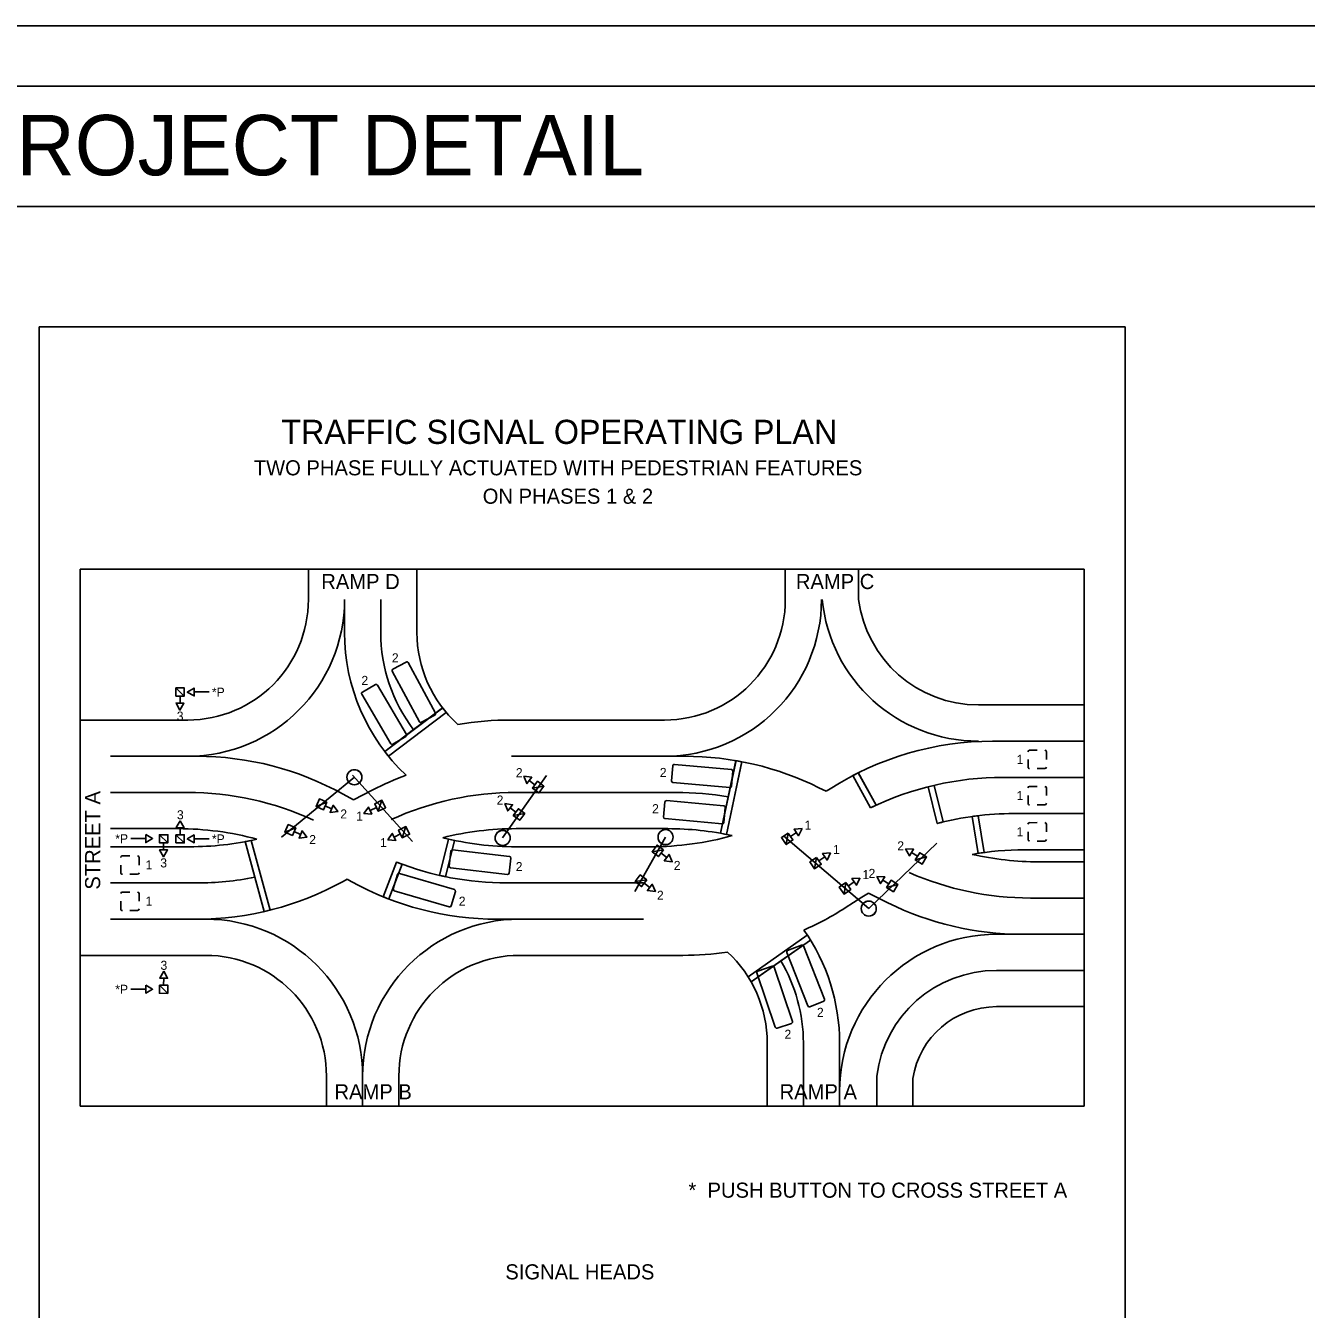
# Model space of a CAD drawing. Extents: x 515543 to 517243, y 660510 to 662861.
# Drawn here: x 516181 to 516712, y 662329 to 662861 of the extents above; entities that cross this region are included whole.
import ezdxf

# ---------------------------------------------------------------- set-up
doc = ezdxf.new("R2010")
doc.units = 0
for name, color, linetype in [('ANNO-SHT', 7, 'Continuous'), ('Default', 7, 'Continuous'), ('DRAINAGE', 7, 'Continuous'), ('Level 1', 7, 'Continuous'), ('Level 62', 7, 'Continuous'), ('SHT-BDR', 7, 'Continuous'), ('SHT-BNDRY', 7, 'Continuous'), ('Signal Design', 7, 'Continuous')]:
    doc.layers.add(name, color=color, linetype=linetype)

# ---------------------------------------------------------------- blocks, each defined once
blk = doc.blocks.new('SC47208')
at = {"layer": 'Level 1'}
blk.add_line((0, 0), (0, 0), dxfattribs=at)
blk = doc.blocks.new('A$C10762150')
at = {"layer": 'Signal Design'}
for p, q in [((-400, -432), (400, 432)), ((-400, -432), (400, 432)), ((-1127, -29), (-415, -14))]:
    blk.add_line(p, q, dxfattribs=at)
for points in [[(-1820, -44), (-1118, -428), (-1135, 370), (-1820, -44), (-1820, -44)], [(-400, -432), (418, -415), (400, 432), (-418, 415), (-400, -432), (-400, -432)]]:
    blk.add_lwpolyline(points, dxfattribs=at)
blk = doc.blocks.new('A$C57205C4C')
at = {"layer": 'Signal Design'}
blk.add_blockref('A$C10762150', (0, 0), dxfattribs=at)

msp = doc.modelspace()

# ---------------------------------------------------------------- linework, layer by layer
at = {"layer": 'Default'}
for p, q in [((516186.87, 662735.88), (516636.87, 662735.88)), ((516186.87, 662735.88), (516186.87, 661900.05)), ((516636.87, 662735.88), (516636.87, 661900.05)), ((516203.87, 662635.52), (516619.86, 662635.52)), ((516203.87, 662413.02), (516203.87, 662635.52)), ((516298.37, 662623.02), (516298.37, 662635.52)), ((516343.37, 662623.02), (516343.37, 662635.52)), ((516495.99, 662623.02), (516495.99, 662635.52)), ((516526.38, 662623.02), (516526.38, 662635.52)), ((516619.86, 662413.02), (516619.86, 662635.52)), ((516313.37, 662609.27), (516313.37, 662623.02)), ((516328.37, 662609.27), (516328.37, 662623.02)), ((516343.37, 662609.27), (516343.37, 662623.02)), ((516251.05, 662584.65), (516257.3, 662584.65)), ((516575.99, 662579.27), (516619.86, 662579.27)), ((516248.37, 662573.02), (516203.87, 662573.02)), ((516354.03, 662578.11), (516330.01, 662560.01)), ((516355.54, 662576.12), (516331.55, 662558.04)), ((516341.99, 662569.04), (516354.03, 662578.11)), ((516393.37, 662573.02), (516382.54, 662573.02)), ((516393.37, 662573.02), (516445.99, 662573.02)), ((516330.01, 662560.01), (516341.99, 662569.04)), ((516581.91, 662564.27), (516619.86, 662564.27)), ((516252.13, 662558.02), (516216.37, 662558.02)), ((516393.37, 662558.02), (516382.54, 662558.02)), ((516393.37, 662558.02), (516454.33, 662558.02)), ((516600.36, 662560.51), (516597.18, 662560.5)), ((516604.18, 662556.71), (516604.17, 662559.89)), ((516469.14, 662526.18), (516475.58, 662556.31)), ((516471.58, 662525.65), (516478.03, 662555.78)), ((516475.56, 662556.21), (516472.36, 662541.24)), ((516596.56, 662556.69), (516596.57, 662553.52)), ((516603.55, 662552.9), (516600.38, 662552.89)), ((516531.33, 662536.64), (516523.97, 662550.06)), ((516533.59, 662537.71), (516526.16, 662551.27)), ((516619.86, 662549.27), (516586.29, 662549.27)), ((516216.37, 662543.02), (516248.25, 662543.02)), ((516312.73, 662542.35), (516317.12, 662539.92)), ((516325.1, 662544.05), (516317.12, 662539.92)), ((516450.81, 662543.02), (516384.45, 662543.02)), ((516472.36, 662541.24), (516469.14, 662526.18)), ((516512.89, 662543.51), (516509.92, 662544.98)), ((516512.89, 662543.51), (516514.58, 662544.59)), ((516558.94, 662530.18), (516555.2, 662545.37)), ((516561.36, 662530.79), (516557.63, 662545.96)), ((516596.56, 662541.69), (516596.57, 662538.52)), ((516600.36, 662545.51), (516597.18, 662545.5)), ((516604.18, 662541.71), (516604.17, 662544.89)), ((516603.55, 662537.9), (516600.38, 662537.89)), ((516575.86, 662517.79), (516573.42, 662533.08)), ((516578.34, 662518.15), (516575.9, 662533.4)), ((516619.86, 662534.27), (516590.67, 662534.27)), ((516600.36, 662530.51), (516597.18, 662530.5)), ((516216.37, 662528.02), (516244.37, 662528.02)), ((516394.62, 662528.02), (516384.45, 662528.02)), ((516447.3, 662528.02), (516394.62, 662528.02)), ((516596.56, 662526.69), (516596.57, 662523.52)), ((516604.18, 662526.71), (516604.17, 662529.89)), ((516216.37, 662520.52), (516249.2, 662520.52)), ((516231.02, 662523.92), (516224.77, 662523.92)), ((516251.05, 662523.82), (516257.3, 662523.82)), ((516272.18, 662522.65), (516280.05, 662493.67)), ((516276.2, 662507.86), (516272.18, 662522.65)), ((516274.64, 662523.13), (516282.49, 662494.26)), ((516356.48, 662523.69), (516352.75, 662508.65)), ((516358.92, 662523.15), (516355.19, 662508.12)), ((516440.38, 662520.52), (516384.45, 662520.52)), ((516437.24, 662520.52), (516433.51, 662520.52)), ((516603.55, 662522.9), (516600.38, 662522.89)), ((516224.44, 662516.75), (516221.26, 662516.74)), ((516228.26, 662512.96), (516228.25, 662516.13)), ((516619.86, 662519.27), (516595.06, 662519.27)), ((516220.64, 662512.93), (516220.65, 662509.76)), ((516227.64, 662509.15), (516224.46, 662509.14)), ((516334.88, 662514.17), (516329.33, 662499.81)), ((516337.21, 662513.28), (516331.66, 662498.91)), ((516619.86, 662514.27), (516601.1, 662514.27)), ((516216.37, 662505.52), (516252.13, 662505.52)), ((516280.05, 662493.67), (516276.2, 662507.86)), ((516312.73, 662506.19), (516314.41, 662507.12)), ((516314.41, 662507.12), (516316.08, 662506.19)), ((516437.24, 662505.52), (516380.57, 662505.52)), ((516224.44, 662501.75), (516221.26, 662501.74)), ((516228.26, 662497.96), (516228.25, 662501.13)), ((516520.86, 662495.2), (516527.73, 662499.59)), ((516538.48, 662497.31), (516530.47, 662501.29)), ((516619.86, 662499.27), (516597.58, 662499.27)), ((516220.64, 662497.93), (516220.65, 662494.76)), ((516227.64, 662494.15), (516224.46, 662494.14)), ((516252.13, 662490.52), (516216.37, 662490.52)), ((516376.69, 662490.52), (516437.24, 662490.52)), ((516505.1, 662483.95), (516480.54, 662466.68)), ((516583.49, 662484.27), (516594.06, 662484.27)), ((516594.06, 662484.27), (516619.86, 662484.27)), ((516506.44, 662481.84), (516481.83, 662464.53)), ((516494.14, 662473.19), (516506.44, 662481.84)), ((516255.87, 662475.52), (516203.87, 662475.52)), ((516385.87, 662475.52), (516453.53, 662475.52)), ((516481.83, 662464.53), (516494.14, 662473.19)), ((516583.49, 662469.27), (516619.86, 662469.27)), ((516231.02, 662461.53), (516224.77, 662461.53)), ((516583.49, 662454.27), (516619.86, 662454.27)), ((516488.49, 662439.27), (516488.49, 662413.02)), ((516503.49, 662439.27), (516503.49, 662413.02)), ((516518.49, 662439.27), (516518.49, 662413.02)), ((516305.87, 662425.52), (516305.87, 662413.02)), ((516320.87, 662425.52), (516320.87, 662413.02)), ((516335.87, 662425.52), (516335.87, 662413.02)), ((516533.88, 662425.52), (516533.88, 662413.02)), ((516548.88, 662424.49), (516548.88, 662413.02)), ((516203.87, 662413.02), (516619.86, 662413.02))]:
    msp.add_line(p, q, dxfattribs=at)
for points in [[(516338.92, 662597.07), (516333.41, 662594.11)], [(516351.02, 662575.9), (516339.76, 662596.82)], [(516333.16, 662593.26), (516344.41, 662572.35)], [(516248.21, 662584.62), (516251.07, 662583.01), (516251.04, 662586.28), (516248.21, 662584.62), (516248.21, 662584.62)], [(516320.52, 662583.71), (516332.52, 662563.21)], [(516326.14, 662587.72), (516320.75, 662584.56)], [(516338.99, 662567), (516327, 662587.5)], [(516353.97, 662578.06), (516330.01, 662560.01)], [(516331.55, 662558.04), (516355.54, 662576.12)], [(516345.26, 662572.09), (516350.76, 662575.06)], [(516333.38, 662562.99), (516338.77, 662566.15)], [(516449.34, 662554.09), (516448.78, 662547.87)], [(516473.68, 662552.52), (516450.02, 662554.66)], [(516475.56, 662556.21), (516469.12, 662526.1)], [(516471.58, 662525.64), (516478.02, 662555.76), (516478.02, 662555.76)], [(516473.68, 662545.61), (516474.24, 662551.84)], [(516449.35, 662547.19), (516473, 662545.05)], [(516523.98, 662550.04), (516531.33, 662536.64)], [(516533.59, 662537.71), (516526.21, 662551.18)], [(516555.2, 662545.37), (516558.94, 662530.18)], [(516561.36, 662530.79), (516557.63, 662545.96)], [(516446.13, 662539.08), (516445.57, 662532.85)], [(516470.47, 662537.5), (516446.81, 662539.64)], [(516470.47, 662530.6), (516471.03, 662536.82)], [(516446.14, 662532.17), (516469.79, 662530.03)], [(516573.42, 662533.08), (516575.86, 662517.79)], [(516578.34, 662518.15), (516575.9, 662533.4)], [(516231.03, 662525.55), (516231, 662522.28), (516233.86, 662523.89), (516231.03, 662525.55), (516231.03, 662525.55)], [(516248.21, 662523.79), (516251.07, 662522.18), (516251.04, 662525.46), (516248.21, 662523.79), (516248.21, 662523.79)], [(516272.18, 662522.65), (516280.05, 662493.67)], [(516282.49, 662494.26), (516274.64, 662523.13)], [(516356.48, 662523.69), (516352.75, 662508.65)], [(516355.19, 662508.12), (516358.92, 662523.15)], [(516357.42, 662518.74), (516356.69, 662512.53)], [(516381.7, 662516.54), (516358.11, 662519.29)], [(516381.52, 662509.64), (516382.25, 662515.84)], [(516334.88, 662514.17), (516329.34, 662499.83)], [(516331.66, 662498.91), (516337.21, 662513.28)], [(516358.88, 662502.81), (516336.1, 662509.51)], [(516357.24, 662511.84), (516380.83, 662509.09)], [(516335.32, 662509.09), (516333.56, 662503.09)], [(516333.98, 662502.32), (516356.76, 662495.62)], [(516357.54, 662496.04), (516359.3, 662502.04)], [(516505.1, 662483.95), (516480.54, 662466.68)], [(516481.83, 662464.53), (516506.44, 662481.84)], [(516502.75, 662479.8), (516496.93, 662477.5)], [(516512.3, 662457.37), (516503.56, 662479.45)], [(516496.58, 662476.69), (516505.33, 662454.61)], [(516484.24, 662468.22), (516491.84, 662445.72)], [(516490.56, 662471.01), (516484.63, 662469.01)], [(516498.95, 662448.12), (516491.35, 662470.62)], [(516231.03, 662463.17), (516231, 662459.89), (516233.86, 662461.51), (516231.03, 662463.17), (516231.03, 662463.17)], [(516506.14, 662454.26), (516511.95, 662456.56)], [(516492.63, 662445.33), (516498.55, 662447.33)]]:
    msp.add_lwpolyline(points, dxfattribs=at)
for centre, radius, start, end in [((516248.37, 662623.02), 50, 270, 0), ((516248.37, 662623.02), 65, 270, 0), ((516445.99, 662623.02), 50, 270, 0), ((516445.99, 662623.02), 65, 270, 0), ((516575.99, 662629.27), 65, 185.5177, 270), ((516575.99, 662629.27), 50, 187.1808, 270), ((516394.62, 662609.27), 81.25, 180, 226.6887), ((516394.62, 662609.27), 66.25, 180, 217.3982), ((516394.62, 662609.27), 51.25, 180, 227.9111), ((516339.21, 662596.52), 0.625, 28.2805, 118.2805), ((516333.71, 662593.56), 0.625, 118.2805, 208.2805), ((516321.06, 662584.02), 0.625, 120.344, 210.344), ((516326.46, 662587.18), 0.625, 30.344, 120.344), ((516350.47, 662575.61), 0.625, 298.2805, 28.2805), ((516394.62, 662609.27), 51.25, 217.5151, 220.3119), ((516382.54, 662433.02), 140, 90, 99.1538), ((516344.96, 662572.64), 0.625, 208.2805, 298.2805), ((516333.06, 662563.53), 0.625, 210.344, 300.344), ((516338.46, 662566.69), 0.625, 300.344, 30.344), ((516581.91, 662439.27), 125, 90, 122.5885), ((516252.13, 662433.02), 125, 60.998, 90), ((516394.62, 662609.27), 81.25, 217.3244, 219.0878), ((516454.33, 662433.02), 125, 63.5977, 90), ((516597.18, 662559.87), 0.635, 90.1884, 180.1884), ((516603.53, 662559.89), 0.635, 0.1884, 90.1884), ((516449.97, 662554.04), 0.625, 84.8206, 174.8206), ((516473.62, 662551.89), 0.625, 354.8206, 84.8206), ((516454.33, 662433.02), 125, 79.076, 80.2224), ((516597.21, 662553.52), 0.635, 180.1884, 270.1884), ((516603.55, 662553.54), 0.635, 270.1884, 0.1884), ((516382.54, 662433.02), 125, 110.4405, 117.3552), ((516449.4, 662547.81), 0.625, 174.8206, 264.8206), ((516581.91, 662439.27), 125, 116.461, 117.6074), ((516586.37, 662423.01), 126.26, 90.036, 115.8442), ((516248.25, 662418.02), 125, 65.263, 90), ((516384.45, 662418.02), 125, 90, 114.4986), ((516450.1, 662403.27), 139.75, 80.8352, 89.7079), ((516473.06, 662545.67), 0.625, 264.8206, 354.8206), ((516586.37, 662423.01), 126.26, 103.1582, 104.2927), ((516597.18, 662544.87), 0.635, 90.1884, 180.1884), ((516603.53, 662544.89), 0.635, 0.1884, 90.1884), ((516446.76, 662539.02), 0.625, 84.8206, 174.8206), ((516470.41, 662536.88), 0.625, 354.8206, 84.8206), ((516586.37, 662423.01), 126.26, 114.7076, 115.8442), ((516597.21, 662538.52), 0.635, 180.1884, 270.1884), ((516603.55, 662538.54), 0.635, 270.1884, 0.1884), ((516446.19, 662532.8), 0.625, 174.8206, 264.8206), ((516469.85, 662530.65), 0.625, 264.8206, 354.8206), ((516590.67, 662409.27), 125, 90, 104.7085), ((516590.67, 662409.27), 125, 103.5626, 104.7085), ((516590.67, 662409.27), 125, 96.788, 97.9345), ((516597.18, 662529.87), 0.635, 90.1884, 180.1884), ((516603.53, 662529.89), 0.635, 0.1884, 90.1884), ((516244.37, 662403.02), 125, 74.8276, 90), ((516384.45, 662403.02), 125, 90, 104.0766), ((516440.38, 662645.52), 125, 270, 285.6177), ((516447.3, 662403.02), 125, 77.6511, 90), ((516447.3, 662403.02), 125, 78.7971, 79.9434), ((516249.2, 662645.52), 125, 270, 282.89), ((516249.2, 662645.52), 125, 280.5938, 281.7426), ((516384.45, 662645.52), 125, 255.9234, 270), ((516384.45, 662645.52), 125, 257.0694, 258.2157), ((516597.21, 662523.52), 0.635, 180.1884, 270.1884), ((516603.55, 662523.54), 0.635, 270.1884, 0.1884), ((516221.26, 662516.11), 0.635, 90.1884, 180.1884), ((516227.61, 662516.13), 0.635, 0.1884, 90.1884), ((516358.04, 662518.67), 0.625, 83.3519, 173.3519), ((516381.63, 662515.92), 0.625, 353.3519, 83.3519), ((516595.06, 662394.27), 125, 90, 99.98), ((516601.1, 662639.27), 125, 257.1954, 270), ((516595.06, 662394.27), 125, 97.688, 98.834), ((516221.29, 662509.76), 0.635, 180.1884, 270.1884), ((516227.63, 662509.78), 0.635, 270.1884, 0.1884), ((516380.57, 662630.52), 125, 248.5589, 249.7048), ((516380.57, 662630.52), 125, 248.5589, 270), ((516335.92, 662508.91), 0.625, 73.6107, 163.6107), ((516357.31, 662512.46), 0.625, 173.3519, 263.3519), ((516380.9, 662509.71), 0.625, 263.3519, 353.3519), ((516597.58, 662624.27), 125, 246.306, 270), ((516252.13, 662630.52), 125, 270, 281.1027), ((516252.13, 662615.52), 125, 270, 299.002), ((516376.69, 662615.52), 125, 240.998, 270), ((516380.57, 662630.52), 125, 257.1393, 258.2857), ((516221.26, 662501.11), 0.635, 90.1884, 180.1884), ((516227.61, 662501.13), 0.635, 0.1884, 90.1884), ((516376.69, 662615.52), 125, 247.7411, 248.8871), ((516334.16, 662502.92), 0.625, 163.6107, 253.6107), ((516358.7, 662502.21), 0.625, 343.6107, 73.6107), ((516595.06, 662394.27), 125, 121.1148, 122.5885), ((516221.29, 662494.76), 0.635, 180.1884, 270.1884), ((516227.63, 662494.78), 0.635, 270.1884, 0.1884), ((516252.13, 662615.52), 125, 282.9083, 284.0548), ((516356.94, 662496.22), 0.625, 253.6107, 343.6107), ((516453.53, 662600.52), 125, 293.6584, 302.5885), ((516594.06, 662609.27), 125, 243.5977, 270), ((516255.87, 662425.52), 65, 0, 90), ((516385.87, 662425.52), 65, 90, 180), ((516437.24, 662439.27), 81.25, 0, 35.1315), ((516437.24, 662439.27), 81.25, 31.6034, 33.3683), ((516583.49, 662419.27), 65, 90, 180), ((516497.17, 662476.92), 0.625, 111.6127, 201.6127), ((516502.98, 662479.22), 0.625, 21.6127, 111.6127), ((516255.87, 662425.52), 50, 0, 90), ((516385.87, 662425.52), 50, 90, 180), ((516453.53, 662600.52), 125, 270, 278.5142), ((516437.24, 662439.27), 51.25, 0, 47.2394), ((516437.24, 662439.27), 66.25, 0, 30.8032), ((516437.24, 662439.27), 51.25, 29.5328, 32.3355), ((516484.83, 662468.42), 0.625, 108.6619, 198.6619), ((516490.76, 662470.42), 0.625, 18.6619, 108.6619), ((516583.49, 662419.27), 50, 90, 172.8275), ((516511.72, 662457.14), 0.625, 291.6127, 21.6127), ((516505.91, 662454.84), 0.625, 201.6127, 291.6127), ((516583.49, 662419.27), 35, 90, 171.4248), ((516492.43, 662445.92), 0.625, 198.6619, 288.6619), ((516498.35, 662447.92), 0.625, 288.6619, 18.6619)]:
    msp.add_arc(centre, radius, start, end, dxfattribs=at)
at = {"layer": 'Level 62'}
msp.add_lwpolyline([(515542.51, 661760.72), (517242.52, 661760.72), (517242.52, 662860.72), (515542.51, 662860.72)], close=True, dxfattribs=at)
at = {"layer": 'SHT-BDR'}
msp.add_lwpolyline([(515667.5, 661835.77), (517167.5, 661835.77), (517167.5, 662785.77), (515667.5, 662785.77)], close=True, dxfattribs=at)
at = {"layer": 'SHT-BNDRY'}
msp.add_lwpolyline([(515605.01, 661785.72), (517217.52, 661785.72), (517217.52, 662835.72), (515605.01, 662835.72)], close=True, dxfattribs=at)
at = {"layer": 'Signal Design'}
for p, q in [((516317.44, 662549.32), (516287.27, 662524.47)), ((516316.63, 662550.22), (516341.52, 662522.72)), ((516397.03, 662550.09), (516378.87, 662524.17)), ((516433.69, 662502.03), (516446.38, 662524.51)), ((516530.57, 662494.89), (516495.28, 662525.07)), ((516530.57, 662494.89), (516558.74, 662521.99))]:
    msp.add_line(p, q, dxfattribs=at)
for centre in [(516317.44, 662549.32), (516378.87, 662524.17), (516446.38, 662524.51), (516530.57, 662494.89)]:
    msp.add_circle(centre, 3.12, dxfattribs=at)
for centre, start, end in [((516317.44, 662549.32), 314.3236, 134.3236), ((516317.44, 662549.32), 134.3236, 314.3236), ((516378.87, 662524.17), 134.3236, 314.3236), ((516378.87, 662524.17), 314.3236, 134.3236), ((516446.38, 662524.51), 134.3236, 314.3236), ((516446.38, 662524.51), 314.3236, 134.3236), ((516530.57, 662494.89), 134.3236, 314.3236), ((516530.57, 662494.89), 314.3236, 134.3236)]:
    msp.add_arc(centre, 3.13, start, end, dxfattribs=at)

# ---------------------------------------------------------------- block references
at = {"layer": 'DRAINAGE', "xscale": 1.0000020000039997, "yscale": 1.0000020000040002, "rotation": -116.41666666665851}
msp.add_blockref('SC47208', (516419.1, 662811.71), dxfattribs=at)
msp.add_blockref('SC47208', (516419.1, 662811.71), dxfattribs=at)
at = {"layer": 'Signal Design'}
for p, xscale, yscale, rotation in [((516245.22, 662584.64), 0.004101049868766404, 0.004101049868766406, 88.26073256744), ((516393.62, 662545.23), 0.004101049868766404, 0.004101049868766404, -38.538733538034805), ((516303.78, 662538.07), 0.004101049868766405, 0.004101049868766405, 155.30458313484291), ((516328.12, 662537.52), 0.004101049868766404, 0.004101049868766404, 24.38547198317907), ((516385.67, 662533.87), 0.004101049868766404, 0.004101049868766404, -38.538733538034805), ((516245.22, 662523.81), 0.004101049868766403, 0.004101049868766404, -91.73926743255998), ((516238.4, 662523.83), 0.004101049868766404, 0.004101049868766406, 88.26073256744), ((516290.9, 662527.46), 0.004101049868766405, 0.004101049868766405, 155.30458313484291), ((516338.03, 662526.57), 0.004101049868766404, 0.004101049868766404, 24.38547198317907), ((516496.77, 662523.82), 0.004101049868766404, 0.004101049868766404, -146.75609784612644), ((516443.17, 662518.82), 0.004101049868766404, 0.004101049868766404, 141.46126646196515), ((516552.2, 662515.69), 0.004101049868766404, 0.004101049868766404, -33.07484385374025), ((516508.55, 662513.74), 0.004101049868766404, 0.004101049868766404, -146.75609784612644), ((516540.3, 662504.26), 0.004101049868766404, 0.004101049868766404, -33.07484385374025), ((516436.19, 662506.45), 0.004101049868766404, 0.004101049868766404, 141.46126646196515), ((516520.74, 662503.32), 0.004101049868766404, 0.004101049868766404, -146.75609784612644), ((516238.4, 662461.46), 0.004101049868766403, 0.004101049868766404, -91.73926743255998)]:
    msp.add_blockref('A$C57205C4C', p, dxfattribs=dict(at, xscale=xscale, yscale=yscale, rotation=rotation))

# ---------------------------------------------------------------- texts
at = {"layer": 'ANNO-SHT'}
msp.add_text('         SPECIAL PROJECT DETAIL         ', height=24.9975, dxfattribs=at).set_placement((515921.08, 662798.73))
at = {"layer": 'Default'}
for s, height, p in [('TRAFFIC SIGNAL OPERATING PLAN', 10, (516287.16, 662687.43)), ('TWO PHASE FULLY ACTUATED WITH PEDESTRIAN FEATURES ', 6.25, (516275.76, 662674.41)), ('ON PHASES 1 & 2', 6.25, (516370.62, 662662.64)), ('RAMP D', 6.25, (516303.73, 662627.29)), ('RAMP C', 6.25, (516500.37, 662627.29)), ('2', 3.75, (516332.98, 662596.93)), ('2', 3.75, (516320.35, 662587.56)), ('*P', 3.75, (516258.4, 662582.71)), ('3', 3.75, (516243.84, 662572.78)), ('1', 3.75, (516591.84, 662554.86)), ('2', 3.75, (516384.35, 662549.35)), ('2', 3.75, (516444.01, 662549.43)), ('2', 3.75, (516376.4, 662537.99)), ('1', 3.75, (516591.84, 662539.86)), ('2', 3.75, (516311.61, 662532.23)), ('2', 3.75, (516440.8, 662534.41)), ('3', 3.75, (516243.93, 662531.89)), ('1', 3.75, (516318.17, 662531.31)), ('1', 3.75, (516503.99, 662527.6)), ('*P', 3.75, (516218.37, 662521.98)), ('*P', 3.75, (516258.4, 662521.88)), ('2', 3.75, (516298.73, 662521.62)), ('1', 3.75, (516591.84, 662524.86)), ('1', 3.75, (516328.07, 662520.36)), ('1', 3.75, (516515.77, 662517.53)), ('2', 3.75, (516542.4, 662519.04)), ('1', 3.75, (516230.93, 662511.13)), ('3', 3.75, (516237.02, 662511.97)), ('2', 3.75, (516449.79, 662510.9)), ('2', 3.75, (516384.29, 662510.42)), ('1', 3.75, (516527.96, 662507.1)), ('2', 3.75, (516530.5, 662507.6)), ('1', 3.75, (516230.93, 662496.13)), ('2', 3.75, (516360.7, 662496.09)), ('2', 3.75, (516442.81, 662498.54)), ('3', 3.75, (516237.11, 662469.54)), ('*P', 3.75, (516218.37, 662459.59)), ('2', 3.75, (516509.11, 662450.03)), ('2', 3.75, (516495.66, 662440.95)), ('RAMP B', 6.25, (516309.2, 662415.89)), ('RAMP A', 6.25, (516493.64, 662415.89)), ('*  PUSH BUTTON TO CROSS STREET A', 6.25, (516455.86, 662375.11)), ('SIGNAL HEADS', 6.25, (516379.98, 662341.27))]:
    msp.add_text(s, height=height, dxfattribs=at).set_placement(p)
msp.add_text('STREET A', height=6.25, rotation=90, dxfattribs=at).set_placement((516212.11, 662502.75))

doc.saveas('drawing.dxf')
